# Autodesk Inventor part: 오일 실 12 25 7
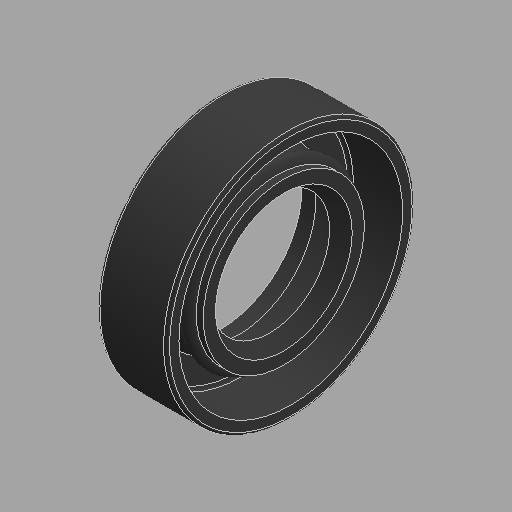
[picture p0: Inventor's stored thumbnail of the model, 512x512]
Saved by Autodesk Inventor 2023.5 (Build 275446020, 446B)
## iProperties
Created: 2026-03
Part Number: 오일 실 12 25 7
Material: 고무
Description: 오일-실
Document SubType Name: Modeling
Designer: mirae
Density: 0.93 g/cm^3
Appearance: 기본값
Author: jhkim
Sending System: Autodesk Inventor 2026
Preprocessor: ST-DEVELOPER v20.1
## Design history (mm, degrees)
node "오일 실 12 25 71"
node "솔리드1"
body "Solid1"
